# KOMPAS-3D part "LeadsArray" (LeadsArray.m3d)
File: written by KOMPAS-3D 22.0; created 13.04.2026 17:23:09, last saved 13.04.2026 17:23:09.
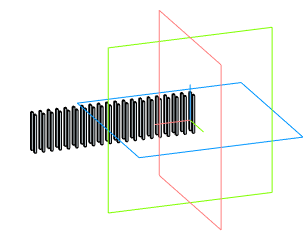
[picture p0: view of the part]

Document properties: Автор: Andrey; Полное имя файла: C:\Users\User1\Documents\LeadsArray.m3d

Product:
- Part/product: LeadsArray

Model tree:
1. Операция без истории:1
2. Операция без истории:2
3. Операция без истории:3
4. Операция без истории:4
5. Операция без истории:5
6. Операция без истории:6
7. Операция без истории:7
8. Операция без истории:8
9. Операция без истории:9
10. Операция без истории:10
11. Операция без истории:11
12. Операция без истории:12
13. Операция без истории:13
14. Операция без истории:14
15. Операция без истории:15
16. Операция без истории:16
17. Операция без истории:17
18. Операция без истории:18
19. Операция без истории:19
20. Операция без истории:20
21. Операция без истории:21
22. Операция без истории:22
23. Операция без истории:23
24. Операция без истории:24
25. Операция без истории:25
26. Операция без истории:26
27. Операция без истории:27
28. Операция без истории:28
29. Операция без истории:29
30. Операция без истории:30
31. Операция без истории:31
32. Операция без истории:32
33. Операция без истории:33
34. Операция без истории:34
35. Операция без истории:35
36. Операция без истории:36
37. Операция без истории:37
38. Операция без истории:38
39. Операция без истории:39
40. Операция без истории:40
